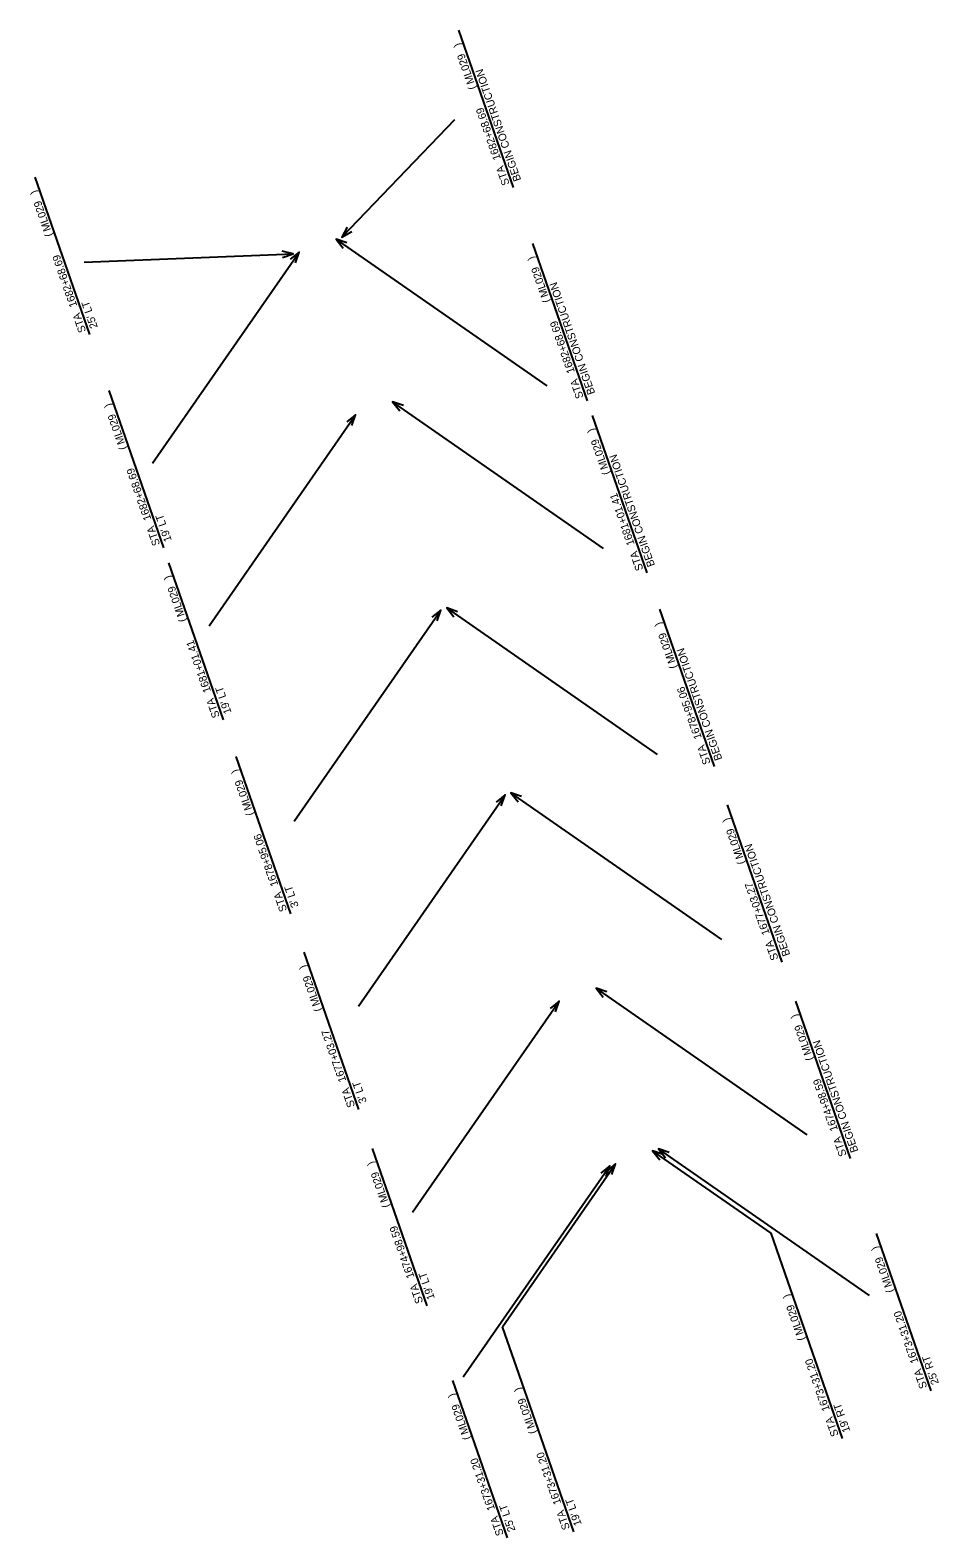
# Model space of a CAD drawing. Extents: x 16415719 to 16419955, y 7114623 to 7121273.
# Drawn here: x 16419072 to 16419955, y 7115326 to 7116790 of the extents above; entities that cross this region are included whole.
import ezdxf

# ---------------------------------------------------------------- set-up
doc = ezdxf.new("R2010")
doc.units = 0
doc.layers.add('SheetBorder', color=7, linetype='Continuous')

msp = doc.modelspace()

# ---------------------------------------------------------------- linework, layer by layer
at = {"layer": 'SheetBorder'}
for p, q in [((16419541.9, 7116637.3), (16419488.8, 7116790.1)), ((16419484.6, 7116702.9), (16419375.3, 7116589.1)), ((16419130.4, 7116494.4), (16419077.4, 7116647.2)), ((16419191.3, 7116369.6), (16419333.7, 7116574.6)), ((16419574.6, 7116444.7), (16419369.6, 7116587.1)), ((16419613.8, 7116430.2), (16419560.7, 7116583)), ((16419124.9, 7116564.8), (16419328, 7116572.7)), ((16419202.3, 7116287.3), (16419149.3, 7116440.1)), ((16419629.5, 7116286.7), (16419424.5, 7116429.1)), ((16419246.2, 7116211.6), (16419388.6, 7116416.6)), ((16419671.8, 7116263.1), (16419618.8, 7116415.8)), ((16419260.4, 7116120.2), (16419207.3, 7116272.9)), ((16419329, 7116021.9), (16419471.4, 7116226.9)), ((16419682.1, 7116086.6), (16419477.1, 7116228.9)), ((16419737.2, 7116074.9), (16419684.1, 7116227.7)), ((16419325.8, 7115932), (16419272.7, 7116084.8)), ((16419391.4, 7115842.3), (16419533.8, 7116047.3)), ((16419744.5, 7115907), (16419539.4, 7116049.3)), ((16419803.2, 7115884.8), (16419750.1, 7116037.6)), ((16419391.8, 7115741.9), (16419338.7, 7115894.7)), ((16419827.3, 7115717.3), (16419622.2, 7115859.6)), ((16419444, 7115642.1), (16419586.4, 7115847.2)), ((16419869.4, 7115694.2), (16419816.3, 7115847)), ((16419458, 7115551.3), (16419404.9, 7115704.1)), ((16419792.4, 7115621.6), (16419677.1, 7115701.6)), ((16419887.8, 7115561.2), (16419682.8, 7115703.6)), ((16419493.2, 7115482.1), (16419635.6, 7115687.2)), ((16419531.4, 7115530.9), (16419641.2, 7115689.1)), ((16419808.6, 7115575.1), (16419792.4, 7115621.6)), ((16419947.7, 7115468.8), (16419894.6, 7115621.5)), ((16419861.6, 7115422.3), (16419808.6, 7115575.1)), ((16419547.5, 7115484.4), (16419531.4, 7115530.9)), ((16419536.3, 7115325.9), (16419483.2, 7115478.6)), ((16419600.6, 7115331.7), (16419547.5, 7115484.4))]:
    msp.add_line(p, q, dxfattribs=at)
for points in [[(16419380.4, 7116598.9), (16419375.3, 7116589.1), (16419384.8, 7116594.6)], [(16419317.5, 7116569.2), (16419328, 7116572.7), (16419317.2, 7116575.3)], [(16419330.1, 7116564.1), (16419333.7, 7116574.6), (16419325.1, 7116567.6)], [(16419380.1, 7116583.5), (16419369.6, 7116587.1), (16419376.6, 7116578.5)], [(16419435, 7116425.5), (16419424.5, 7116429.1), (16419431.5, 7116420.5)], [(16419385, 7116406.1), (16419388.6, 7116416.6), (16419380, 7116409.6)], [(16419467.8, 7116216.4), (16419471.4, 7116226.9), (16419462.8, 7116219.9)], [(16419487.6, 7116225.3), (16419477.1, 7116228.9), (16419484.1, 7116220.3)], [(16419530.2, 7116036.8), (16419533.8, 7116047.3), (16419525.2, 7116040.3)], [(16419549.9, 7116045.7), (16419539.4, 7116049.3), (16419546.5, 7116040.7)], [(16419632.7, 7115856), (16419622.2, 7115859.6), (16419629.3, 7115851)], [(16419582.8, 7115836.7), (16419586.4, 7115847.2), (16419577.8, 7115840.1)], [(16419687.6, 7115698), (16419677.1, 7115701.6), (16419684.2, 7115693)], [(16419693.3, 7115700), (16419682.8, 7115703.6), (16419689.8, 7115695)], [(16419632, 7115676.7), (16419635.6, 7115687.2), (16419627, 7115680.1)], [(16419637.7, 7115678.6), (16419641.2, 7115689.1), (16419632.6, 7115682.1)]]:
    msp.add_lwpolyline(points, dxfattribs=at)

# ---------------------------------------------------------------- texts
for s, p in [(')', (16419491.6, 7116775.2)), ('ML029', (16419504.1, 7116739)), ('BEGIN CONSTRUCTION', (16419549.6, 7116644.7)), (' (', (16419506.9, 7116731.2)), ('1682+68.69', (16419529.8, 7116665.3)), ('STA ', (16419538.3, 7116640.7)), (')', (16419080.2, 7116632.3)), ('ML029', (16419092.7, 7116596.1)), (' (', (16419095.4, 7116588.3)), ('1682+68.69', (16419118.3, 7116522.4)), (')', (16419563.5, 7116568.1)), ('ML029', (16419576.1, 7116532)), ('BEGIN CONSTRUCTION', (16419621.5, 7116437.6)), (' (', (16419578.8, 7116524.2)), ('STA ', (16419126.9, 7116497.8)), ("25' LT", (16419138.2, 7116501.8)), ('1682+68.69', (16419601.7, 7116458.2)), ('STA ', (16419610.2, 7116433.7)), (')', (16419152.1, 7116425.2)), ('ML029', (16419164.6, 7116389.1)), (')', (16419621.6, 7116401)), (' (', (16419167.4, 7116381.3)), ('ML029', (16419634.1, 7116364.8)), ('BEGIN CONSTRUCTION', (16419679.6, 7116270.4)), ('1682+68.69', (16419190.3, 7116315.3)), (' (', (16419636.8, 7116357)), ('1681+01.41', (16419659.8, 7116291)), ("19' LT", (16419210.1, 7116294.7)), ('STA ', (16419198.8, 7116290.8)), ('STA ', (16419668.3, 7116266.5)), (')', (16419210.1, 7116258.1)), ('ML029', (16419222.7, 7116221.9)), (' (', (16419225.4, 7116214.1)), (')', (16419686.9, 7116212.8)), ('1681+01.41', (16419248.3, 7116148.1)), ('ML029', (16419699.5, 7116176.6)), ('BEGIN CONSTRUCTION', (16419745, 7116082.3)), (' (', (16419702.2, 7116168.8)), ("19' LT", (16419268.2, 7116127.5)), ('1678+95.06', (16419725.1, 7116102.9)), ('STA ', (16419256.8, 7116123.6)), ('STA ', (16419733.6, 7116078.3)), (')', (16419275.5, 7116069.9)), ('ML029', (16419288, 7116033.8)), (' (', (16419290.8, 7116025.9)), (')', (16419752.9, 7116022.7)), ('1678+95.06', (16419313.7, 7115960)), ('ML029', (16419765.5, 7115986.6)), ('BEGIN CONSTRUCTION', (16419811, 7115892.2)), (' (', (16419768.2, 7115978.7)), ('1677+03.27', (16419791.1, 7115912.8)), ('STA ', (16419322.2, 7115935.4)), ("3' LT", (16419333.5, 7115939.4)), ('STA ', (16419799.6, 7115888.2)), (')', (16419341.5, 7115879.8)), ('ML029', (16419354.1, 7115843.7)), (' (', (16419356.8, 7115835.8)), (')', (16419819.1, 7115832.1)), ('1677+03.27', (16419379.7, 7115769.9)), ('ML029', (16419831.7, 7115796)), ('BEGIN CONSTRUCTION', (16419877.2, 7115701.6)), (' (', (16419834.4, 7115788.1)), ("3' LT", (16419399.6, 7115749.3)), ('1674+98.59', (16419857.3, 7115722.2)), ('STA ', (16419388.2, 7115745.3)), ('STA ', (16419865.8, 7115697.7)), (')', (16419407.7, 7115689.2)), ('ML029', (16419420.3, 7115653.1)), (' (', (16419423, 7115645.3)), ('1674+98.59', (16419445.9, 7115579.3)), (')', (16419897.4, 7115606.7)), ('ML029', (16419910, 7115570.5)), ("19' LT", (16419465.7, 7115558.7)), ('STA ', (16419454.4, 7115554.8)), (' (', (16419912.7, 7115562.7)), (')', (16419811.4, 7115560.2)), ('ML029', (16419823.9, 7115524.1)), ('1673+31.20', (16419935.6, 7115496.7)), (' (', (16419826.6, 7115516.2)), ('1673+31.20', (16419849.5, 7115450.3)), ('STA ', (16419944.1, 7115472.2)), ("25' RT", (16419955.5, 7115476.1)), (')', (16419486, 7115463.8)), (')', (16419550.3, 7115469.6)), ('ML029', (16419562.9, 7115433.4)), ('ML029', (16419498.6, 7115427.6)), ("19' RT", (16419869.4, 7115429.7)), (' (', (16419565.6, 7115425.6)), ('STA ', (16419858.1, 7115425.7)), (' (', (16419501.3, 7115419.8)), ('1673+31.20', (16419524.2, 7115353.8)), ('1673+31.20', (16419588.5, 7115359.6)), ("19' LT", (16419608.4, 7115339)), ('STA ', (16419532.7, 7115329.3)), ("25' LT", (16419544.1, 7115333.2)), ('STA ', (16419597, 7115335.1))]:
    msp.add_text(s, height=7.5, rotation=109.1528, dxfattribs=at).set_placement(p)

doc.saveas('drawing.dxf')
